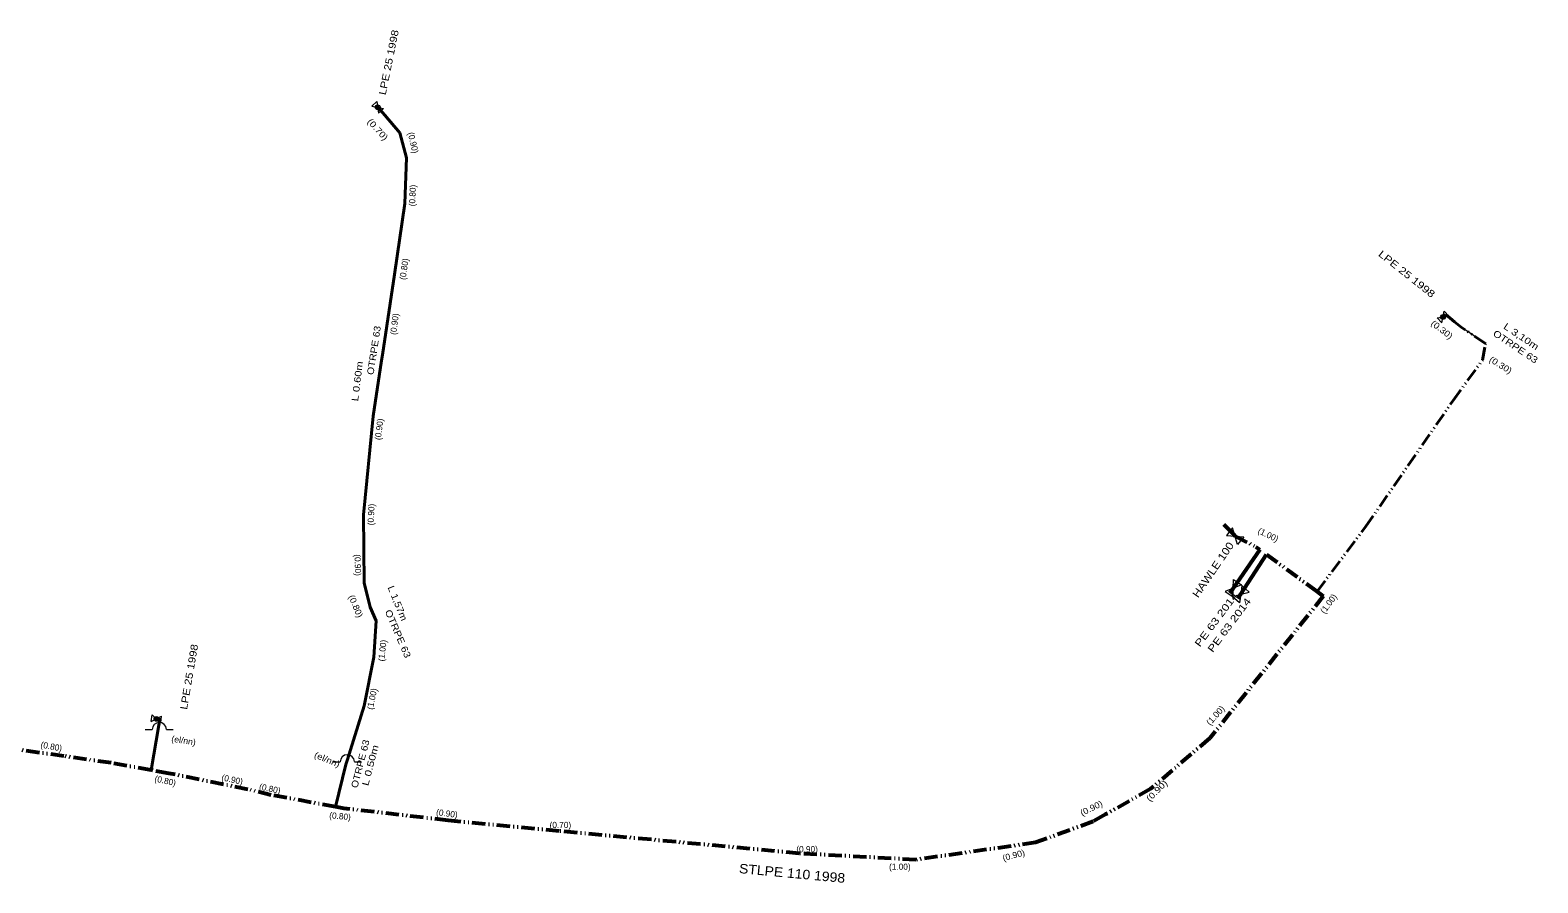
# Model space of a CAD drawing. Extents: x -648036 to -642998, y -1161549 to -1158141.
# Drawn here: x -644171.4 to -644012.6, y -1160279.2 to -1160189.4 of the extents above; entities that cross this region are included whole.
import ezdxf
from ezdxf.enums import TextEntityAlignment as Align

# ---------------------------------------------------------------- set-up
doc = ezdxf.new("R2010")
doc.units = 0
doc.header["$LTSCALE"] = 0.28
doc.linetypes.add('DASH_DOUBLE_DOT', pattern=[9.2, 5, -1.2, 0.3, -1.2, 0.3, -1.2])
for name, color, linetype, lineweight in [('12', 7, 'DASH_DOUBLE_DOT', 40), ('14', 7, 'Continuous', 13), ('15', 7, 'Continuous', 13), ('19', 7, 'Continuous', 13), ('8', 7, 'Continuous', 53)]:
    doc.layers.add(name, color=color, linetype=linetype, lineweight=lineweight)
for name, color, linetype in [('20', 7, 'Continuous'), ('22', 7, 'Continuous'), ('24', 7, 'Continuous'), ('27', 7, 'Continuous'), ('35', 7, 'Continuous')]:
    doc.layers.add(name, color=color, linetype=linetype)

msp = doc.modelspace()

# ---------------------------------------------------------------- linework, layer by layer
at = {"layer": '12', "linetype": 'Continuous'}
for points in [[(-644139.2, -1160271.2), (-644138.11, -1160266.74), (-644137.94, -1160266.21), (-644136.19, -1160260.55), (-644135.18, -1160255.43), (-644134.93, -1160251.61), (-644135.56, -1160250.17), (-644136.19, -1160247.62), (-644136.27, -1160240.46), (-644135.23, -1160230.04), (-644134.35, -1160224.2), (-644134.26, -1160223.61), (-644132.98, -1160215.12), (-644131.9, -1160207.66), (-644131.71, -1160202.84), (-644132.41, -1160200.22), (-644134, -1160198.34), (-644134.76, -1160197.52)], [(-644158.61, -1160267.34), (-644157.8, -1160262.59), (-644157.71, -1160261.99), (-644158.06, -1160261.94)]]:
    msp.add_lwpolyline(points, dxfattribs=at)
at = {"layer": '12'}
msp.add_lwpolyline([(-644035.84, -1160248.52), (-644030.72, -1160241.7), (-644021.51, -1160228.41), (-644018.43, -1160224.16), (-644018.08, -1160222.42), (-644020.65, -1160220.68), (-644021.36, -1160220.12), (-644022.28, -1160219.33), (-644022.57, -1160219.61)], dxfattribs=at)
at = {"layer": '14'}
for p, q in [((-644018.08, -1160222.42), (-644020.65, -1160220.68)), ((-644134.26, -1160223.61), (-644134.35, -1160224.2)), ((-644135.56, -1160250.17), (-644134.93, -1160251.61)), ((-644138.11, -1160266.74), (-644137.94, -1160266.21))]:
    msp.add_line(p, q, dxfattribs=at)
at = {"layer": '15'}
for p, q in [((-644135.364, -1160197.392), (-644134.841, -1160196.908)), ((-644135.364, -1160197.392), (-644134.156, -1160197.648)), ((-644134.841, -1160196.908), (-644134.679, -1160198.131)), ((-644134.679, -1160198.131), (-644134.156, -1160197.648)), ((-644023.18, -1160219.704), (-644021.961, -1160219.517)), ((-644022.685, -1160220.216), (-644023.18, -1160219.704)), ((-644022.685, -1160220.216), (-644022.455, -1160219.004)), ((-644021.961, -1160219.517), (-644022.455, -1160219.004)), ((-644158.609, -1160262.221), (-644158.509, -1160261.516)), ((-644158.609, -1160262.221), (-644157.511, -1160261.659)), ((-644158.509, -1160261.516), (-644157.612, -1160262.364)), ((-644157.612, -1160262.364), (-644157.511, -1160261.659)), ((-644159.235, -1160263.055), (-644158.5, -1160263.054)), ((-644157.014, -1160263.054), (-644156.28, -1160263.055)), ((-644139.435, -1160266.455), (-644138.7, -1160266.454)), ((-644137.214, -1160266.454), (-644136.48, -1160266.455))]:
    msp.add_line(p, q, dxfattribs=at)
for points in [[(-644044.471, -1160242.694), (-644043.555, -1160242.779), (-644044.198, -1160243.571), (-644044.745, -1160241.816), (-644045.387, -1160242.609)], [(-644044.66, -1160248.17), (-644044.647, -1160247.251), (-644043.807, -1160247.829), (-644045.514, -1160248.511), (-644044.673, -1160249.089)], [(-644043.88, -1160248.81), (-644044.007, -1160249.721), (-644044.769, -1160249.042), (-644042.991, -1160248.577), (-644043.753, -1160247.899)]]:
    msp.add_lwpolyline(points, close=True, dxfattribs=at)
for centre in [(-644157.7574, -1160263.0546), (-644137.9574, -1160266.4546)]:
    msp.add_arc(centre, 0.7431, 1.2748, 179.83951, dxfattribs=at)
at = {"layer": '19'}
for centre, radius in [((-644134.76, -1160197.52), 0.25), ((-644134.76, -1160197.52), 0.17), ((-644134.76, -1160197.52), 0.09), ((-644022.57, -1160219.61), 0.25), ((-644022.57, -1160219.61), 0.17), ((-644022.57, -1160219.61), 0.09), ((-644158.06, -1160261.94), 0.25), ((-644158.06, -1160261.94), 0.17), ((-644158.06, -1160261.94), 0.09)]:
    msp.add_circle(centre, radius, dxfattribs=at)
at = {"layer": '8', "linetype": 'DASH_DOUBLE_DOT'}
for p, q in [((-644044.66, -1160242.46), (-644045.66, -1160241.48)), ((-644044.66, -1160242.46), (-644044.471, -1160242.694)), ((-644041.175, -1160244.612), (-644035.84, -1160248.52))]:
    msp.add_line(p, q, dxfattribs=at)
for points in [[(-644044.471, -1160242.694), (-644042.27, -1160243.81), (-644041.866, -1160244.106)], [(-644035.84, -1160248.52), (-644035.18, -1160249), (-644047.12, -1160263.97), (-644053.37, -1160269.31), (-644058.15, -1160272.02), (-644059.41, -1160272.74), (-644065.47, -1160274.97), (-644078.08, -1160276.77), (-644090.36, -1160276.11), (-644115.63, -1160273.75), (-644127.34, -1160272.64), (-644138.31, -1160271.36), (-644139.2, -1160271.2)], [(-644158.61, -1160267.34), (-644162.84, -1160266.58), (-644167.8, -1160265.86), (-644173.39, -1160265.07), (-644180.55, -1160264.28), (-644183.61, -1160263.97)], [(-644139.2, -1160271.2), (-644145.96, -1160269.96), (-644148.43, -1160269.36), (-644156.74, -1160267.68), (-644158.61, -1160267.34)]]:
    msp.add_lwpolyline(points, dxfattribs=at)
at = {"layer": '8'}
for points in [[(-644041.866, -1160244.106), (-644044.66, -1160248.17), (-644044.77, -1160248.36), (-644044.82, -1160248.42), (-644045.042, -1160248.697)], [(-644044.184, -1160249.272), (-644044, -1160248.99), (-644043.96, -1160248.9), (-644043.88, -1160248.81), (-644041.175, -1160244.612)]]:
    msp.add_lwpolyline(points, dxfattribs=at)

# ---------------------------------------------------------------- texts
at = {"layer": '20', "width": 1.1}
msp.add_text('STLPE 110 1998', height=1, rotation=354.661, dxfattribs=at).set_placement((-644091.162, -1160278.6908), align=Align.CENTER)
at = {"layer": '22'}
for s, rotation, width, p in [('LPE 25 1998', 78.495, 1.2, (-644133.227, -1160192.8693)), ('LPE 25 1998', 321.429, 1.25, (-644026.6193, -1160215.3722)), ('PE 63 2014', 53.165, 1.3, (-644046.1421, -1160251.7003)), ('PE 63 2014', 53.165, 1.3, (-644044.7781, -1160252.2833)), ('LPE 25 1998', 80.214, 1.2, (-644154.2515, -1160257.5727))]:
    msp.add_text(s, height=0.75, rotation=rotation, dxfattribs=dict(at, width=width)).set_placement(p, align=Align.CENTER)
at = {"layer": '24'}
for s, rotation, width, p in [('OTRPE 63', 81.36, 1.15, (-644134.8123, -1160223.1721)), ('OTRPE 63', 326.013, 1.2, (-644015.1372, -1160223.0251)), ('L 3,10m', 326.013, 1.25, (-644014.5312, -1160221.9566)), ('L 0.60m', 83.079, 1.25, (-644136.5649, -1160226.4182)), ('L 1,57m', 292.208, 1.15, (-644132.9904, -1160249.8862)), ('OTRPE 63', 293.354, 1.2, (-644132.9437, -1160253.1043)), ('OTRPE 63', 75.63, 1.15, (-644136.2521, -1160266.7549)), ('L 0.50m', 75.63, 1.3, (-644135.2064, -1160266.9129))]:
    msp.add_text(s, height=0.7, rotation=rotation, dxfattribs=dict(at, width=width)).set_placement(p, align=Align.CENTER)
at = {"layer": '27'}
for s, rotation, width, p in [('(0.70)', 312.262, 1.2, (-644134.9953, -1160200.0754)), ('(0.30)', 322.575, 1.15, (-644022.889, -1160221.1972)), ('(0.30)', 328.305, 1.15, (-644016.6733, -1160224.9414)), ('(0.80)', 292.781, 1.1, (-644137.3647, -1160250.1937)), ('(1.00)', 48.128, 1.05, (-644046.297, -1160261.7874)), ('(el/nn)', 351.223, 1.05, (-644155.2446, -1160264.529)), ('(el/nn)', 337.472, 1.15, (-644140.2045, -1160266.5111)), ('(0.90)', 45.264, 1.2, (-644052.4868, -1160269.7252)), ('(0.90)', 26.356, 1.1, (-644059.4598, -1160271.6254)), ('(0.90)', 14.897, 1.05, (-644067.6981, -1160276.615))]:
    msp.add_text(s, height=0.65, rotation=rotation, dxfattribs=dict(at, width=width)).set_placement(p, align=Align.CENTER)
for s, rotation, p in [('(0.90)', 283.041, (-644131.336, -1160201.3317)), ('(0.80)', 87.663, (-644130.7744, -1160206.8288)), ('(0.80)', 81.933, (-644131.6611, -1160214.6051)), ('(0.90)', 82.506, (-644132.6686, -1160220.3914)), ('(0.90)', 82.506, (-644134.2886, -1160231.4714)), ('(0.90)', 87.09, (-644135.134, -1160240.4275)), ('(1.00)', 334.034, (-644041.1278, -1160242.8367)), ('(0.90)', 271.582, (-644137.1728, -1160245.7445)), ('(1.00)', 53.858, (-644034.3632, -1160249.9967)), ('(1.00)', 83.079, (-644133.9448, -1160254.7762)), ('(1.00)', 77.922, (-644135.04, -1160259.895)), ('(0.80)', 349.504, (-644169.1802, -1160265.1588)), ('(0.80)', 347.212, (-644157.1974, -1160268.769)), ('(0.90)', 347.785, (-644150.1433, -1160268.6425)), ('(0.80)', 347.785, (-644146.1808, -1160269.5989)), ('(0.80)', 354.661, (-644138.7512, -1160272.5018)), ('(0.90)', 352.369, (-644127.5107, -1160272.2118))]:
    msp.add_text(s, height=0.65, rotation=rotation, dxfattribs=at).set_placement(p, align=Align.CENTER)
for s, p in [('(0.70)', (-644115.52, -1160273.43)), ('(0.90)', (-644089.5395, -1160275.98)), ('(1.00)', (-644079.7705, -1160277.83))]:
    msp.add_text(s, height=0.65, dxfattribs=at).set_placement(p, align=Align.CENTER)
at = {"layer": '35', "width": 1.15}
msp.add_text('HAWLE 100', height=0.8, rotation=55.561, dxfattribs=at).set_placement((-644046.4562, -1160246.4552), align=Align.CENTER)

doc.saveas('drawing.dxf')
